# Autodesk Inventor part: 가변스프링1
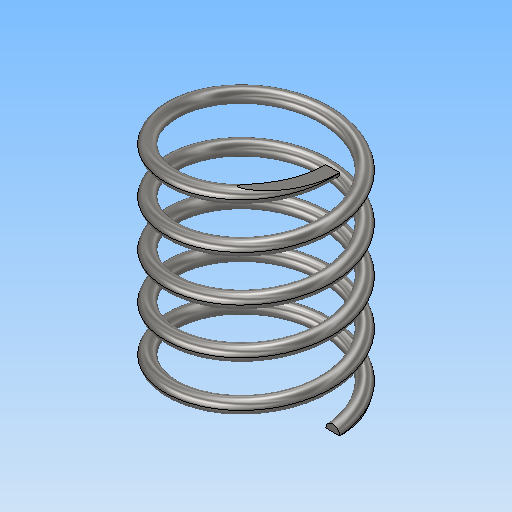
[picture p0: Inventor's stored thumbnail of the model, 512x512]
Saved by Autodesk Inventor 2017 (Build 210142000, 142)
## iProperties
Part Number: 가변스프링1
Material: 강철, 연강
Document SubType Name: Modeling
Designer: MRC
Density: 7.85 g/cm^3
Appearance: 반연마
Mass: 8.38973 g
Surface Area: 21.6696 cm^2
Volume: 1.06876 cm^3
Author: MRC
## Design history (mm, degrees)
sketch "스케치1"
  geometry: L1 (0, 0)-(0, -32.68); L2 (0, 0)-(11, 0); L3 (0, -32.68)-(11.069, -32.68); C1 r 1 at (11, 0)
  constraints: 6 end point, 2 horizontal, 1 centre point, 1 coincident, 1 vertical
  dimensions: "d1" = 22 diameter of L2.end L1; "d2" = 2 diameter of C1; "d4" = 32.68047 distance of L1.start L1.end (derived)
feature "코일1" sketch "스케치1" pitch "d5" = 10; turns "d7" = 5; dims "d6" = 32.68047 (= d4), "d8" = 0, angle "d9" = 90 deg, angle "d10" = 90 deg, "d11" = 0, "d12" = 0
sketch "스케치2"
  geometry: L1 (0, 13.296)-(-32.68, 13.296); L2 (-32.68, 13.296)-(-32.68, -12.495); L3 (-32.68, -12.495)-(0, -12.495); L4 (0, -12.495)-(0, 13.296); 1 further point
  constraints: 8 end point, 2 parallel, 1 horizontal, 1 perpendicular, 1 point on line
  dimensions: "d17" = 32.68047 distance of L2.end L3.end (= d4)
extrude "돌출1" sketch "스케치2" stored distance "d15" = 30; taper "d16" = 0 deg
node "솔리드1"
